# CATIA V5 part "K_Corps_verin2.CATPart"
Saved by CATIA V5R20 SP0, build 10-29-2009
Part number: Corps_verin2
Bounding box of the stored display mesh (mm): x -21 to 21, y 218.162 to 232.36, z 113.181 to 138.622
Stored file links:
  G:\Khaled_CFAO_2011\ST2M\ST2M_GR1\hgrenier\Khaled\CAD_ThinkMOTION\K_Corps_verin2.CATPart
  C:\Users\Tom\Documents\Cours 2A\CFAO\Projet thinkmotion\Hugo\porte_outil.CATProduct
  G:\Khaled_CFAO_2011\ST2M\ST2M_GR1\hgrenier\Khaled\CAD_ThinkMOTION\K_Squelette.CATPart
  G:\Khaled_CFAO_2011\ST2M\ST2M_GR1\hgrenier\Khaled\CAD_ThinkMOTION\K_Godet.CATPart
  G:\Khaled_CFAO_2011\ST2M\ST2M_GR1\hgrenier\CATIA\Bras.CATPart
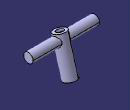
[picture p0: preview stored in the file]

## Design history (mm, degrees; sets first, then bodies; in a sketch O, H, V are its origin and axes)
External parameters (linked from other documents)
  External.Rayon = 3 mm
Set1
  Plane1 "plan_sym": linked copy from another document
  Point1 "Centre_godet/verin2": linked copy from another document
  Point2 "Centre_verin2/tête": linked copy from another document
  Plane2 "Plan_godet": linked copy from another document
Body1 (main body)
  Sketch1 on Plane1, origin (0, 0, 0), H (0, 1, 0), V (0, 0, 1)
    axis line L1 (235.708, 89.158) -> (223.049, 133.683)
    point P1 (235.708, 89.158)
    point P2 (223.049, 133.683)
    reference projected point E1 (223.049, 133.683) from Point1
    reference projected point E2 (235.708, 89.158) from Point2
    point P3 (232.3645, 115.3366)
    line L2 (232.3645, 115.3366) -> (225.744, 138.6228)
    point P4 (225.744, 138.6228)
    line L3 (225.744, 138.6228) -> (224.0329, 138.1363)
    point P5 (225.744, 138.6228)
    point P7 (232.3645, 115.3366)
    line L4 (232.3645, 115.3366) -> (230.6534, 114.8501)
    line L5 (230.6534, 114.8501) -> (224.0329, 138.1363)
    coincidence: P2 E1, P1 E2, P7 L2, P3 P7, P4 P5
    perpendicularity: L3 L2
    parallelism: L4 L3, L5 L1
  Shaft1: profile Sketch1, axis Sketch1.L1, angle 360
  Sketch2 on Plane1, origin (0, 0, 0), H (0, 1, 0), V (0, 0, 1)
    circle A1 centre (223.049, 133.683) radius 3
    point P1 (223.049, 133.683)
    reference projected point E1 (223.049, 133.683) from Point1
    radius A1 = 3 {= External.Rayon}
    coincidence: P1 E1
  Pad1: profile Sketch2, direction (1, 0, 0), up to Plane2, opposite side length 21
  Loft1: solid, Sections (edge [face of Shaft1 from Sketch1.L5 | face of Shaft1 from Sketch1.L4]; edge [face of Shaft1 from Sketch1.L3 | face of Shaft1 from Sketch1.L5])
